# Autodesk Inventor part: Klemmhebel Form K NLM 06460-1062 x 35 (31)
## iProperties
Title: Klemmhebel Form K NLM 06460-1062 x 35 (31)
Author: AGeddert
Created: 2002-10
Part Number: Klemmhebel M6x35
Document SubType Name: Modellieren
Designer: AGeddert
Company: Cadenas Solutions GmbH
Length Units: 11269
Angle Units: 11283
Time Units: 11279
Mass Units: 11290
Length Display Precision: 3
Angle Display Precision: 1
Compacted: False
PropertySet Name: _Private Model Information
Control State: 0
Master: False
Checked Out: False
PropertySet Name: Design Tracking Control
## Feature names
1. Drehung1 [Revolution]
2. Extrusion1
3. Extrusion2
4. Extrusion3
5. Extrusion4
